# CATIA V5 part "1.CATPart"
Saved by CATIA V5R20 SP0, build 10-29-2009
Part number: 1
Bounding box of the stored display mesh (mm): x -175 to 175, y -175 to 175, z 0 to 30
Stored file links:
  E:\Ehsan\Amoozesh\CATIA\CATIA Course\Advanced\Exercises\DMU Kinematic\13\1.CATPart
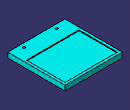
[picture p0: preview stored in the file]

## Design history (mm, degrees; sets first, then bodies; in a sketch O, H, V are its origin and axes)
Body1 (main body)
  Sketch1 on xy-plane, origin (0, 0, 0), H (1, 0, 0), V (0, 1, 0)
    line L1 (175, 175) -> (175, -175)
    line L2 (175, -175) -> (-175, -175)
    line L3 (-175, -175) -> (-175, 175)
    line L4 (-175, 175) -> (175, 175)
    length L4 = 350
    length L1 = 350
    vertical: L1 V, L3 V
    horizontal: L2 H, L4 H
    equidistance: L1 L3 O, L2 L4 O
  Pad1: profile Sketch1, direction (0, 0, 1), length 30
  Sketch2 on end face of Pad1, origin (0, 0, 30), H (1, 0, 0), V (0, 1, 0)
    line L1 (160, 160) -> (160, -75)
    line L2 (160, -75) -> (-160, -75)
    line L3 (-160, -75) -> (-160, 160)
    line L4 (-160, 160) -> (160, 160)
    reference projected line E1 (175, 175) -> (-175, 175) from edge [face of Pad1 from Sketch1.L4 | end face of Pad1]
    reference projected line E2 (175, -250) -> (175, 250) from edge [face of Pad1 from Sketch1.L1 | end face of Pad1]
    reference projected line E3 (-175, -175) -> (175, -175) from edge [face of Pad1 from Sketch1.L2 | end face of Pad1]
    distance L4 E1 = 15
    distance L1 E2 = 15
    distance L2 E3 = 100
    vertical: L1 V, L3 V
    horizontal: L2 H, L4 H
    equidistance: L1 L3 O
  Pocket1: profile Sketch2, direction (0, 0, -1), length 5
  Sketch3 on end face of Pad1, origin (0, 0, 30), H (1, 0, 0), V (0, 1, 0)
    circle A1 centre (100, -150) radius 7.5
    point P1 (100, -150)
    point P2 (-100, -150)
    circle A2 centre (-100, -150) radius 7.5
    radius A1 = 7.5
    distance P1 P2 = 200
    distance P1 H = 150
    symmetry: A1 A2 V
  Pocket2: profile Sketch3, direction (0, 0, -1), through (limit type 6)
